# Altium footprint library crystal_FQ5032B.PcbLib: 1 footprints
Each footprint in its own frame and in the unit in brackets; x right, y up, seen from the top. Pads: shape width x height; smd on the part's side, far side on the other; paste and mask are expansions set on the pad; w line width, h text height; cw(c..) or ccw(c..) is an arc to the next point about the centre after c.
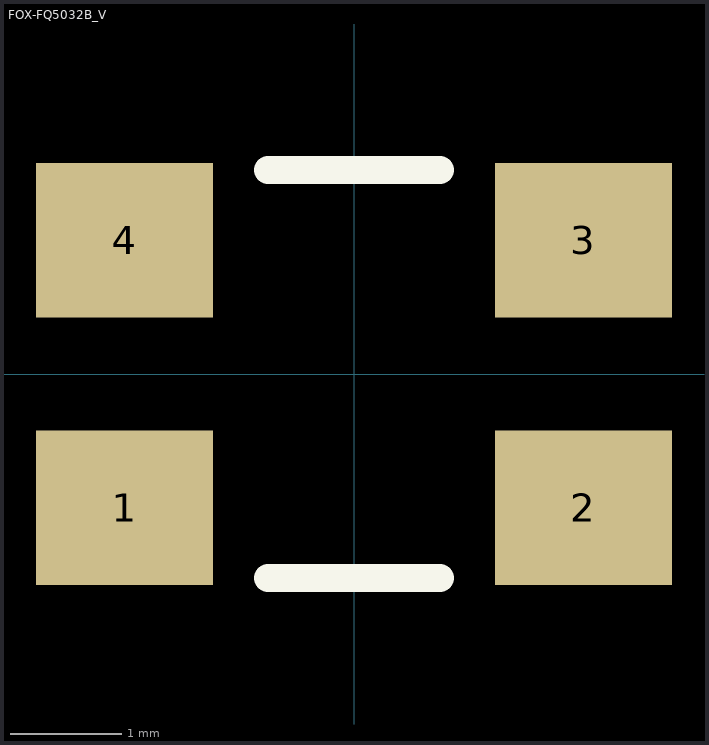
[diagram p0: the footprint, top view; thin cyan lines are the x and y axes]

## FOX-FQ5032B_V [mil] "SMT Crystal, 4-Leads, Body 5.2x3.4mm"
pads (4):
  rect 63x55 smd: 1(-81.5,-47.5) 2(81.5,-47.5) 3(81.5,47.5) 4(-81.5,47.5)
Top Overlay:
  lines w10: -30.5,-72.5 30.5,-72.5 ; -30.5,72.5 30.5,72.5
3D body: height 47.24, standoff 0, extent -114.46,-46.87 113.11,46.73
3D body: height 19.68, standoff 0, extent 62.19,-52.22 97.74,-26.01
3D body: height 19.68, standoff 0, extent -103.01,-51.67 -67.46,-25.46
3D body: height 19.68, standoff 0, extent 67.17,24.91 102.72,51.12
3D body: height 19.68, standoff 0, extent -97.83,24.91 -62.28,51.12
